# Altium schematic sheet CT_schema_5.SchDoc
size 287 x 163 mm
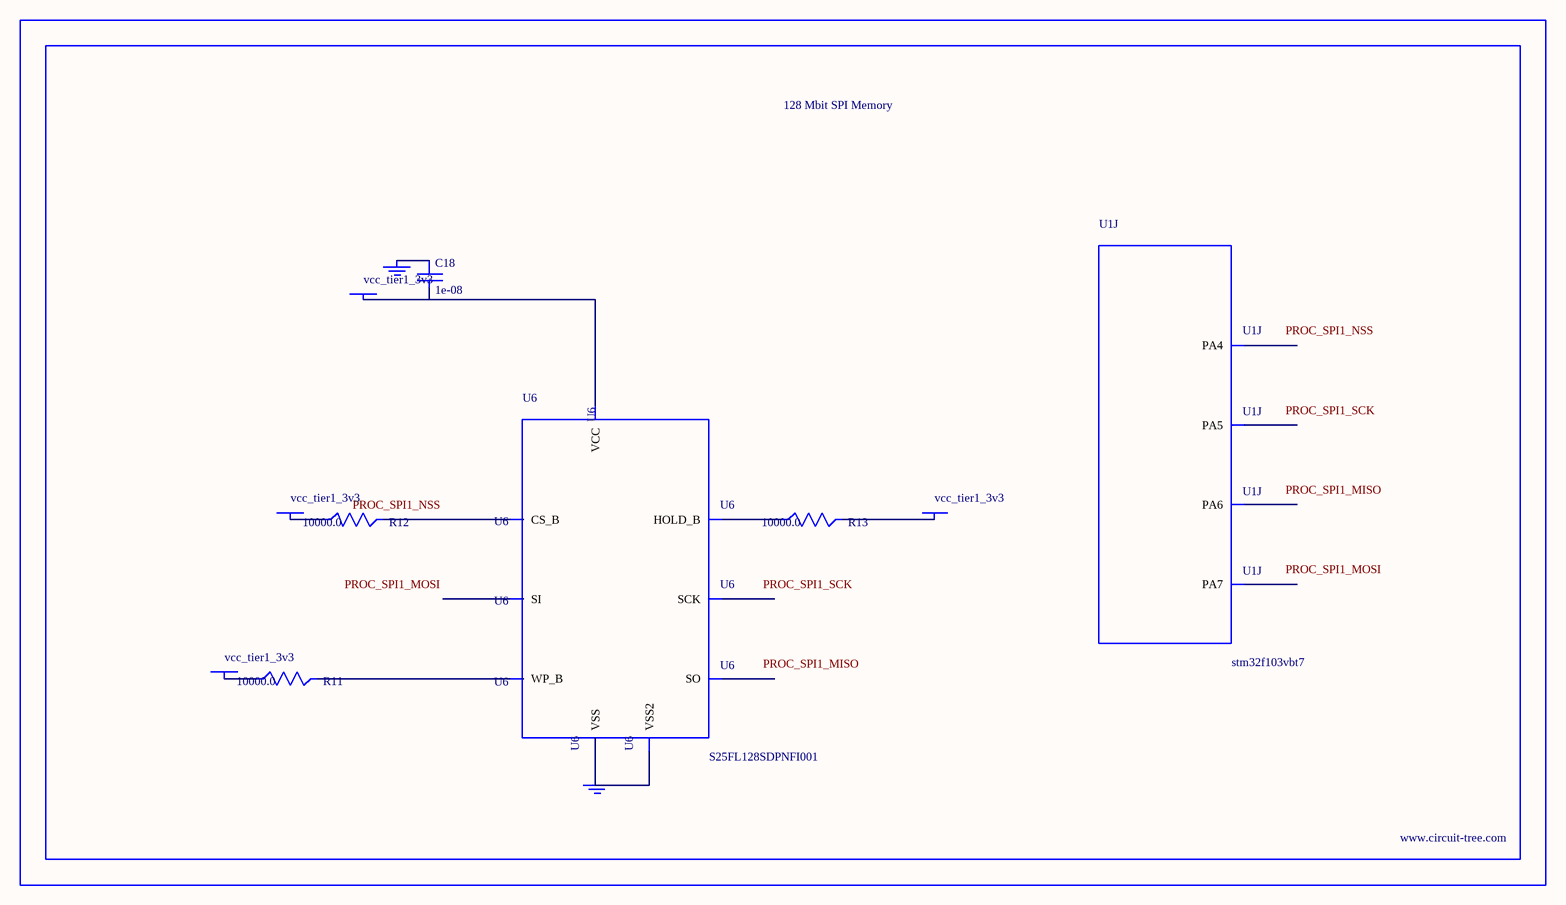
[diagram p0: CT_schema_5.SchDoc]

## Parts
BORDER4  (no value)
C18  1e-08  [C0402]
GND_INSTANCE_4_0  (no value)
GND_INSTANCE_4_1  (no value)
POWER_INSTANCE_4_0  vcc_tier1_3v3
POWER_INSTANCE_4_1  vcc_tier1_3v3
POWER_INSTANCE_4_2  vcc_tier1_3v3
POWER_INSTANCE_4_3  vcc_tier1_3v3
R11  10000.0  [R0603]
R12  10000.0  [R0603]
R13  10000.0  [R0603]
U1  stm32f103vbt7  [LQFP100]  (part J of 11)
U6  S25FL128SDPNFI001  [WNG008]

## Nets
NetC18_1: C18.1 GND_INSTANCE_4_0.0(GND)
NetC18_2: C18.2 POWER_INSTANCE_4_3.0(PWR) U6.8(VCC)
NetGND_INSTANCE_4_1_0: GND_INSTANCE_4_1.0(GND) U6.4(VSS) U6.PAD(VSS2)
NetPOWER_INSTANCE_4_0_0: POWER_INSTANCE_4_0.0(PWR) R12.1
NetPOWER_INSTANCE_4_1_0: POWER_INSTANCE_4_1.0(PWR) R11.1
NetPOWER_INSTANCE_4_2_0: POWER_INSTANCE_4_2.0(PWR) R13.2
NetR11_2: R11.2 U6.3(WP_B)
NetR12_2: R12.2 U6.1(CS_B)
NetR13_1: R13.1 U6.7(HOLD_B)

Not connected (* = marked no-connect by the designer): U1 29(PA4) 30(PA5) 31(PA6) 32(PA7); U6 2(SO) 5(SI) 6(SCK)

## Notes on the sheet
- Labels drawn without touching a wire or pin: PROC_SPI1_MISO, PROC_SPI1_MOSI, PROC_SPI1_NSS, PROC_SPI1_SCK

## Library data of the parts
BORDER4 = BORDER_PAGE4
C18 = C0402C103K3RAC
GND_INSTANCE_4_0 GND_INSTANCE_4_1 = GND
POWER_INSTANCE_4_0-POWER_INSTANCE_4_3 = PWR
R11-R13 = RC0603JR-0710KL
